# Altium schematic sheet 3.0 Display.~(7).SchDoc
size A4; SheetNumber: 3; SheetTotal: 6
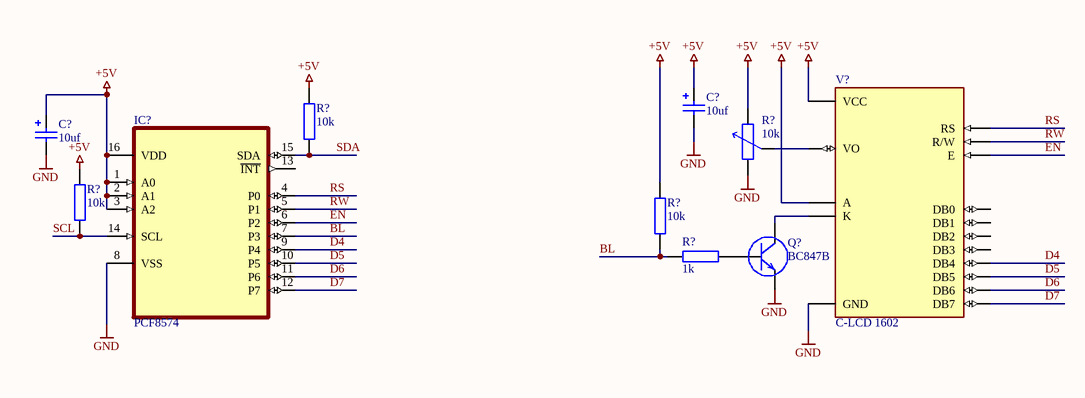
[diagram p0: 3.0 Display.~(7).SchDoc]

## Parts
(Parts that share a designator on the sheet are numbered #1, #2 ... from top to bottom, then left to right.)
C?#1  10uf  [C_SMD_D-TYP]
C?#2  10uf  [C_SMD_D-TYP]
IC?  PCF8574  [SO-16]
Q?  BC847B  [SOT-23]
R?#1  10k  [R_SMD_0805]
R?#2  10k  [R_THT_POT-TP-.2/.4]
R?#3  10k  [R_SMD_0805]
R?#4  10k  [R_SMD_0805]
R?#5  1k  [R_SMD_0805]
V?  C-LCD 1602  [V_MODULE_LCD-16X2]

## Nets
+5V: C?#1.1 C?#2.1 IC?.1(A0) IC?.2(A1) IC?.3(A2) IC?.16(VDD) R?#1.2 R?#2.2 R?#3.2 R?#4.2 V?.2(VCC) V?.15(A)
GND: C?#1.2 C?#2.2 IC?.8(VSS) Q?.2(E) R?#2.1 V?.1(GND)
BL: IC?.7(P3) R?#4.1 R?#5.1
D4: IC?.9(P4) V?.11(DB4)
D5: IC?.10(P5) V?.12(DB5)
D6: IC?.11(P6) V?.13(DB6)
D7: IC?.12(P7) V?.14(DB7)
EN: IC?.6(P2) V?.6(E)
RS: IC?.4(P0) V?.4(RS)
RW: IC?.5(P1) V?.5(R/W)
SCL: IC?.14(SCL) R?#3.1
SDA: IC?.15(SDA) R?#1.1
NetQ?_1: Q?.1(B) R?#5.2
NetQ?_3: Q?.3(C) V?.16(K)
NetR?#2_3: R?#2.3 V?.3(VO)

Not connected (* = marked no-connect by the designer): IC? 13(~{INT}); V? 7(DB0) 8(DB1) 9(DB2) 10(DB3)

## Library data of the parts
C?#1 C?#2 = C_SMD_ELK: SMD Elektrolytkondensator
IC? = IC_PCF8574: I/O Expander
Q? = Q_SMD_NPN: NPN Transistor
R?#1 R?#3-R?#5 = R_SMD_Widerstand: Widerstand SMD
R?#2 = R_THT_Potentiometer: Potentiometer; Set Position: 0.5
V? = V_C-LCD-1602: LC-Display; MF: Gravitech; MP: LCD-16X2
